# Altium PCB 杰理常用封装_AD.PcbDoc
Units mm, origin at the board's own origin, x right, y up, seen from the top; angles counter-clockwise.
Board outline 121.28 x 58.04 mm, 2 copper layers (Top, Bottom), stack 0.069 mm thick; 26 components, 0 nets, 451 pads, 0 vias.
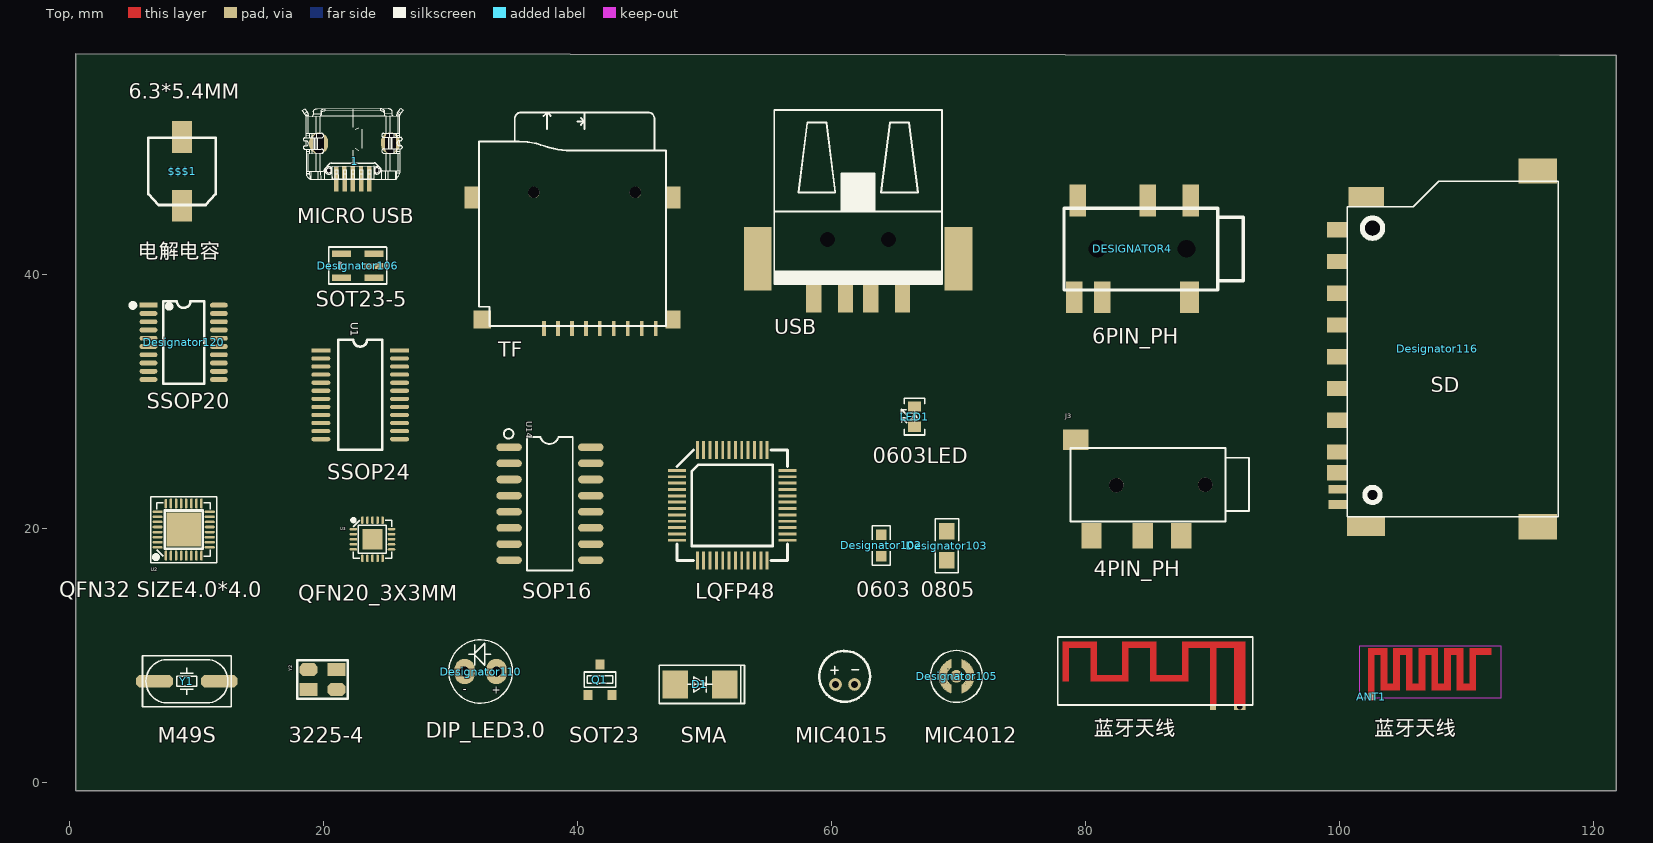
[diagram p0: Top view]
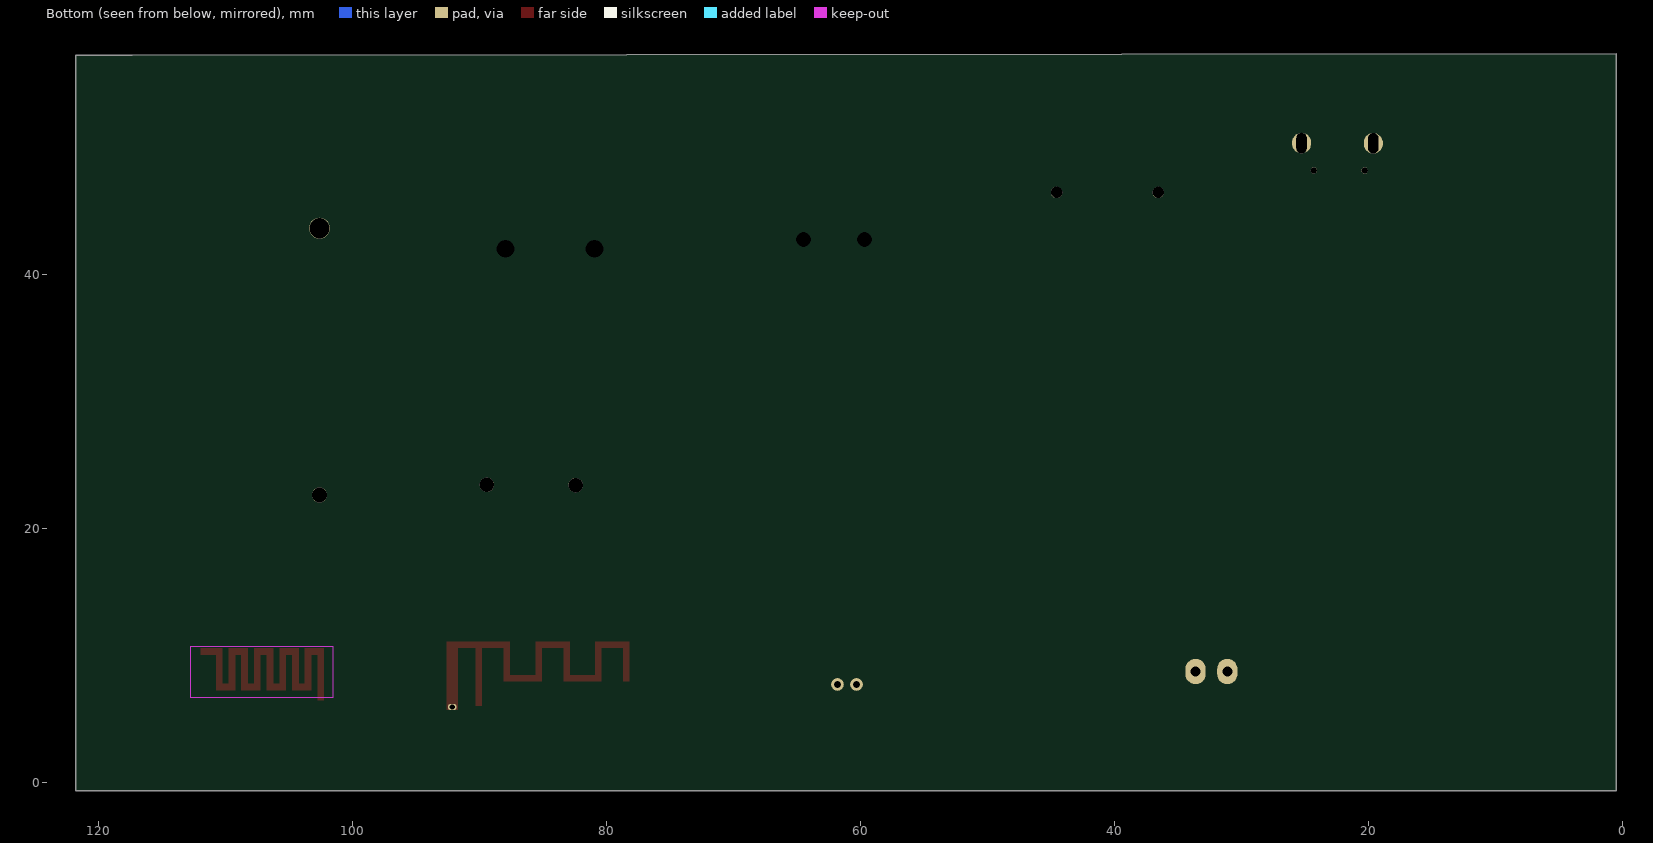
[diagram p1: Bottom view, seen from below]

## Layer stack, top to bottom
Top: signal copper 0.0343
Bottom: signal copper 0.0343

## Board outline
0.508,57.404 0.508,-0.635 10.922,-0.635 121.793,-0.635 121.793,11.43 121.793,57.277 117.348,57.277

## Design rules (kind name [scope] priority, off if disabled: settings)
Clearance "'Default' PADS rule_18" [All] p1: gap=0.3
Clearance "'Default' PADS rule_15" [IsVia vs IsVia] p2: gap=0.305
ComponentClearance "'Default' PADS rule_12" [All] p1: gap=0 collisioncheckmode=3 verticalgap=0.254 showdistances=FALSE
FlightTimeFalling "'Default' PADS rule_10" [All] p1: maximum=10.00g
FlightTimeRising "'Default' PADS rule_9" [All] p1: maximum=10.00g
Length "'Default' PADS rule_5" [All] p1: maxlimit=1270 minlimit=0
MatchedLengths "'Default' PADS rule_11" [InNetClass('All Nets')] p1: tolerance=5.08 checknetsindiffpair=TRUE checkdiffpairvsdiffpair=TRUE checkothers=TRUE
MaxMinImpedance "'Default' PADS rule_8" [All] p1: minimum=50.00 maximum=150.0
ParallelSegment "'Default' PADS rule_7" [All] p1: limit=25.4 gap=5.08
ParallelSegment "'Default' PADS rule_6" [All] p2: limit=25.4 gap=5.08
PlaneClearance "'Default' PADS rule_14" [All] p1: clearance=0.3
PlaneConnect "Power Plane Connect Style - pads with no thermal" [(Name='1-8') Or (Name='1-9') Or (Name='A1-1') Or (Name='A2-1') Or (Name='A3-1') Or (Name='DESIGNATOR4-7') Or (Name='DESIGNATOR4-8') Or (Name='TF1-14') Or (Name='TF1-15') Or (Name='USB1-0') Or (Name='USB1-0/2')] p1: planeconnectstyle=NoConnect reliefexpansion=0.508 reliefentries=4 reliefconductorwidth=0.254 reliefairgap=0.254 // PAD - No Thermal Connect Rule
PlaneConnect "Power Plane Connect Style - Via from round thru-hole global defaults" [IsVia] p2: planeconnectstyle=Direct reliefexpansion=0.508 reliefentries=4 reliefconductorwidth=0.254 reliefairgap=0.254
PlaneConnect "Power Plane Connect Style - Round thru-hole pad from global defaults" [IsPad And OnMultiLayer And (PadShape_MidLayer1 = 'Round') And (PadXSize_MidLayer1 = PadYSize_MidLayer1)] p3: planeconnectstyle=Direct reliefexpansion=0.508 reliefentries=4 reliefconductorwidth=0.254 reliefairgap=0.254
PlaneConnect "Power Plane Connect Style - Square thru-hole pad from global defaults" [IsPad And OnMultiLayer And ((PadShape_MidLayer1 = 'Rectangular') Or (PadShape_MidLayer1 = 'Octagonal') Or (PadShape_MidLayer1 = 'Rounded Rectangle')) And (PadXSize_MidLayer1 = PadYSize_MidLayer1)] p4: planeconnectstyle=Direct reliefexpansion=0.508 reliefentries=4 reliefconductorwidth=0.254 reliefairgap=0.254
PlaneConnect "Power Plane Connect Style - Rect thru-hole pad from global defaults" [IsPad And OnMultiLayer And ((PadShape_MidLayer1 = 'Rectangular') Or (PadShape_MidLayer1 = 'Octagonal') Or (PadShape_MidLayer1 = 'Rounded Rectangle')) And (PadXSize_MidLayer1 <> PadYSize_MidLayer1)] p5: planeconnectstyle=Direct reliefexpansion=0.508 reliefentries=4 reliefconductorwidth=0.254 reliefairgap=0.254
PlaneConnect "Power Plane Connect Style - Square-rect thru-hole pad from global defaults" [IsPad And OnMultiLayer And (PadShape_MidLayer1 = 'Rounded Rectangle') And (PadXSize_MidLayer1 = PadYSize_MidLayer1) And (Pad_CornerRadius_MidLayer1 = '0%')] p6: planeconnectstyle=Direct reliefexpansion=0.508 reliefentries=4 reliefconductorwidth=0.254 reliefairgap=0.254
PlaneConnect "Power Plane Connect Style - Oval thru-hole pad from global defaults" [IsPad And OnMultiLayer And (PadShape_MidLayer1 = 'Round') And (PadXSize_MidLayer1 <> PadYSize_MidLayer1)] p7: planeconnectstyle=Direct reliefexpansion=0.508 reliefentries=4 reliefconductorwidth=0.254 reliefairgap=0.254
PlaneConnect "Power Plane Connect Style - Round-oval thru-hole pad from global defaults" [IsPad And OnMultiLayer And (PadShape_MidLayer1 = 'Rounded Rectangle') And (PadXSize_MidLayer1 = PadYSize_MidLayer1) And (Pad_CornerRadius_MidLayer1 = '100%')] p8: planeconnectstyle=Direct reliefexpansion=0.508 reliefentries=4 reliefconductorwidth=0.254 reliefairgap=0.254
PolygonConnect "Polygon Connect Style - Bottom Round SMD from global defaults" [IsSMTPin And (PadShape_BottomLayer = 'Round') And (PadXSize_BottomLayer = PADYSize_BottomLayer) vs Layer = 'Bottom'] p1: connectstyle=Direct reliefconductorwidth=0.254 reliefentries=4 polygonreliefangle="45 Angle" airgapwidth=0.254
PolygonConnect "Polygon Connect Style - Top Round SMD from global defaults" [IsSMTPin And (PadShape_TopLayer = 'Round') And (PadXSize_TopLayer = PADYSize_TopLayer) vs Layer = 'Top'] p2: connectstyle=Direct reliefconductorwidth=0.254 reliefentries=4 polygonreliefangle="45 Angle" airgapwidth=0.254
PolygonConnect "Polygon Connect Style - Bottom Square SMD from global defaults 1" [IsSMTPin And (PadShape_BottomLayer = 'Rectangular') And (PadXSize_BottomLayer = PADYSize_BottomLayer) vs Layer = 'Bottom'] p3: connectstyle=Direct reliefconductorwidth=0.254 reliefentries=4 polygonreliefangle="45 Angle" airgapwidth=0.254
PolygonConnect "Polygon Connect Style - Bottom Square SMD from global defaults 2" [IsSMTPin And (PadShape_BottomLayer = 'Octagonal') And (PadXSize_BottomLayer = PADYSize_BottomLayer) vs Layer = 'Bottom'] p4: connectstyle=Direct reliefconductorwidth=0.254 reliefentries=4 polygonreliefangle="45 Angle" airgapwidth=0.254
PolygonConnect "Polygon Connect Style - Bottom Square SMD from global defaults 3" [IsSMTPin And (PadShape_BottomLayer = 'Rounded Rectangle') And (PadXSize_BottomLayer = PADYSize_BottomLayer) vs Layer = 'Bottom'] p5: connectstyle=Direct reliefconductorwidth=0.254 reliefentries=4 polygonreliefangle="45 Angle" airgapwidth=0.254
PolygonConnect "Polygon Connect Style - Top Square SMD from global defaults 1" [IsSMTPin And (PadShape_TopLayer = 'Rectangular') And (PadXSize_TopLayer = PADYSize_TopLayer) vs Layer = 'Top'] p6: connectstyle=Direct reliefconductorwidth=0.254 reliefentries=4 polygonreliefangle="45 Angle" airgapwidth=0.254
PolygonConnect "Polygon Connect Style - Top Square SMD from global defaults 2" [IsSMTPin And (PadShape_TopLayer = 'Octagonal') And (PadXSize_TopLayer = PADYSize_TopLayer) vs Layer = 'Top'] p7: connectstyle=Direct reliefconductorwidth=0.254 reliefentries=4 polygonreliefangle="45 Angle" airgapwidth=0.254
PolygonConnect "Polygon Connect Style - Top Square SMD from global defaults 3" [IsSMTPin And (PadShape_TopLayer = 'Rounded Rectangle') And (PadXSize_TopLayer = PADYSize_TopLayer) vs Layer = 'Top'] p8: connectstyle=Direct reliefconductorwidth=0.254 reliefentries=4 polygonreliefangle="45 Angle" airgapwidth=0.254
PolygonConnect "Polygon Connect Style - Bottom Rect SMD from global defaults 1" [IsSMTPin And (PadShape_BottomLayer = 'Rectangular') And (PadXSize_BottomLayer <> PADYSize_BottomLayer) vs Layer = 'Bottom'] p9: connectstyle=Direct reliefconductorwidth=0.254 reliefentries=4 polygonreliefangle="45 Angle" airgapwidth=0.254
PolygonConnect "Polygon Connect Style - Bottom Rect SMD from global defaults 2" [IsSMTPin And (PadShape_BottomLayer = 'Octagonal') And (PadXSize_BottomLayer <> PADYSize_BottomLayer) vs Layer = 'Bottom'] p10: connectstyle=Direct reliefconductorwidth=0.254 reliefentries=4 polygonreliefangle="45 Angle" airgapwidth=0.254
PolygonConnect "Polygon Connect Style - Bottom Rect SMD from global defaults 3" [IsSMTPin And (PadShape_BottomLayer = 'Rounded Rectangle') And (PadXSize_BottomLayer <> PADYSize_BottomLayer) vs Layer = 'Bottom'] p11: connectstyle=Direct reliefconductorwidth=0.254 reliefentries=4 polygonreliefangle="45 Angle" airgapwidth=0.254
PolygonConnect "Polygon Connect Style - Bottom Square-rect SMD pad from global defaults" [IsSMTPin And (PadShape_BottomLayer = 'Rounded Rectangle') And (PadXSize_BottomLayer = PADYSize_BottomLayer) And (Pad_CornerRadius_BottomLayer = '0%') vs Layer = 'Bottom'] p12: connectstyle=Direct reliefconductorwidth=0.254 reliefentries=4 polygonreliefangle="45 Angle" airgapwidth=0.254
PolygonConnect "Polygon Connect Style - Top Rect SMD from global defaults 1" [IsSMTPin And (PadShape_TopLayer = 'Rectangular') And (PadXSize_TopLayer <> PADYSize_TopLayer) vs Layer = 'Top'] p13: connectstyle=Direct reliefconductorwidth=0.254 reliefentries=4 polygonreliefangle="45 Angle" airgapwidth=0.254
PolygonConnect "Polygon Connect Style - Top Rect SMD from global defaults 2" [IsSMTPin And (PadShape_TopLayer = 'Octagonal') And (PadXSize_TopLayer <> PADYSize_TopLayer) vs Layer = 'Top'] p14: connectstyle=Direct reliefconductorwidth=0.254 reliefentries=4 polygonreliefangle="45 Angle" airgapwidth=0.254
PolygonConnect "Polygon Connect Style - Top Rect SMD from global defaults 3" [IsSMTPin And (PadShape_TopLayer = 'Rounded Rectangle') And (PadXSize_TopLayer <> PADYSize_TopLayer) vs Layer = 'Top'] p15: connectstyle=Direct reliefconductorwidth=0.254 reliefentries=4 polygonreliefangle="45 Angle" airgapwidth=0.254
PolygonConnect "Polygon Connect Style - Top Square-rect SMD pad from global defaults" [IsSMTPin And (PadShape_TopLayer = 'Rounded Rectangle') And (PadXSize_TopLayer = PADYSize_TopLayer) And (Pad_CornerRadius_TopLayer = '0%') vs Layer = 'Top'] p16: connectstyle=Direct reliefconductorwidth=0.254 reliefentries=4 polygonreliefangle="45 Angle" airgapwidth=0.254
PolygonConnect "Polygon Connect Style - Bottom Oval SMD from global defaults" [IsSMTPin And (PadShape_BottomLayer = 'Round') And (PadXSize_BottomLayer <> PADYSize_BottomLayer) vs Layer = 'Bottom'] p17: connectstyle=Direct reliefconductorwidth=0.254 reliefentries=4 polygonreliefangle="45 Angle" airgapwidth=0.254
PolygonConnect "Polygon Connect Style - Bottom Round-oval SMD pad from global defaults" [IsSMTPin And (PadShape_BottomLayer = 'Rounded Rectangle') And (PadXSize_BottomLayer = PADYSize_BottomLayer) And (Pad_CornerRadius_BottomLayer = '100%') vs Layer = 'Bottom'] p18: connectstyle=Direct reliefconductorwidth=0.254 reliefentries=4 polygonreliefangle="45 Angle" airgapwidth=0.254
PolygonConnect "Polygon Connect Style - Top Oval SMD from global defaults" [IsSMTPin And (PadShape_TopLayer = 'Round') And (PadXSize_TopLayer <> PADYSize_TopLayer) vs Layer = 'Top'] p19: connectstyle=Direct reliefconductorwidth=0.254 reliefentries=4 polygonreliefangle="45 Angle" airgapwidth=0.254
PolygonConnect "Polygon Connect Style - Top Round-oval SMD pad from global defaults" [IsSMTPin And (PadShape_TopLayer = 'Rounded Rectangle') And (PadXSize_TopLayer = PADYSize_TopLayer) And (Pad_CornerRadius_TopLayer = '100%') vs Layer = 'Top'] p20: connectstyle=Direct reliefconductorwidth=0.254 reliefentries=4 polygonreliefangle="45 Angle" airgapwidth=0.254
PolygonConnect "Polygon Connect Style - Via from round thru-hole global defaults_19" [IsVia] p21: connectstyle=Direct reliefconductorwidth=0.254 reliefentries=4 polygonreliefangle="45 Angle" airgapwidth=0.254
PolygonConnect "Polygon Connect Style - Bottom Round thru-hole pad from global defaults" [IsPad And OnMultiLayer And (PadShape_BottomLayer = 'Round') And (PadXSize_BottomLayer = PADYSize_BottomLayer) vs Layer = 'Bottom'] p22: connectstyle=Direct reliefconductorwidth=0.254 reliefentries=4 polygonreliefangle="45 Angle" airgapwidth=0.254
PolygonConnect "Polygon Connect Style - Via from round thru-hole global defaults" [IsVia] p23: connectstyle=Direct reliefconductorwidth=0.254 reliefentries=4 polygonreliefangle="45 Angle" airgapwidth=0.254
PolygonConnect "Polygon Connect Style - Top Round thru-hole pad from global defaults" [IsPad And OnMultiLayer And (PadShape_TopLayer = 'Round') And (PadXSize_TopLayer = PADYSize_TopLayer) vs Layer = 'Top'] p24: connectstyle=Direct reliefconductorwidth=0.254 reliefentries=4 polygonreliefangle="45 Angle" airgapwidth=0.254
PolygonConnect "Polygon Connect Style - Bottom Square thru-hole pad from global defaults" [IsPad And OnMultiLayer And ((PadShape_BottomLayer = 'Rectangular') Or (PadShape_BottomLayer = 'Octagonal') Or (PadShape_BottomLayer = 'Rounded Rectangle')) And (PadXSize_BottomLayer = PADYSize_BottomLayer) vs Layer = 'Bottom'] p25: connectstyle=Direct reliefconductorwidth=0.254 reliefentries=4 polygonreliefangle="45 Angle" airgapwidth=0.254
PolygonConnect "Polygon Connect Style - Top Square thru-hole pad from global defaults" [IsPad And OnMultiLayer And ((PadShape_TopLayer = 'Rectangular') Or (PadShape_TopLayer = 'Octagonal') Or (PadShape_TopLayer = 'Rounded Rectangle')) And (PadXSize_TopLayer = PADYSize_TopLayer) vs Layer = 'Top'] p26: connectstyle=Direct reliefconductorwidth=0.254 reliefentries=4 polygonreliefangle="45 Angle" airgapwidth=0.254
PolygonConnect "Polygon Connect Style - Bottom Rect thru-hole pad from global defaults" [IsPad And OnMultiLayer And ((PadShape_BottomLayer = 'Rectangular') Or (PadShape_BottomLayer = 'Octagonal') Or (PadShape_BottomLayer = 'Rounded Rectangle')) And (PadXSize_BottomLayer <> PADYSize_BottomLayer) vs Layer = 'Bottom'] p27: connectstyle=Direct reliefconductorwidth=0.254 reliefentries=4 polygonreliefangle="45 Angle" airgapwidth=0.254
PolygonConnect "Polygon Connect Style - Bottom Square-rect thru-hole pad from global defaults" [IsPad And OnMultiLayer And (PadShape_BottomLayer = 'Rounded Rectangle') And (PadXSize_BottomLayer = PADYSize_BottomLayer) And (Pad_CornerRadius_BottomLayer = '0%') vs Layer = 'Bottom'] p28: connectstyle=Direct reliefconductorwidth=0.254 reliefentries=4 polygonreliefangle="45 Angle" airgapwidth=0.254
PolygonConnect "Polygon Connect Style - Top Rect thru-hole pad from global defaults" [IsPad And OnMultiLayer And ((PadShape_TopLayer = 'Rectangular') Or (PadShape_TopLayer = 'Octagonal') Or (PadShape_TopLayer = 'Rounded Rectangle')) And (PadXSize_TopLayer <> PADYSize_TopLayer) vs Layer = 'Top'] p29: connectstyle=Direct reliefconductorwidth=0.254 reliefentries=4 polygonreliefangle="45 Angle" airgapwidth=0.254
PolygonConnect "Polygon Connect Style - Top Square-rect thru-hole pad from global defaults" [IsPad And OnMultiLayer And (PadShape_TopLayer = 'Rounded Rectangle') And (PadXSize_TopLayer = PADYSize_TopLayer) And (Pad_CornerRadius_TopLayer = '0%') vs Layer = 'Top'] p30: connectstyle=Direct reliefconductorwidth=0.254 reliefentries=4 polygonreliefangle="45 Angle" airgapwidth=0.254
PolygonConnect "Polygon Connect Style - Bottom Oval thru-hole pad from global defaults" [IsPad And OnMultiLayer And (PadShape_BottomLayer = 'Round') And (PadXSize_BottomLayer <> PADYSize_BottomLayer) vs Layer = 'Bottom'] p31: connectstyle=Direct reliefconductorwidth=0.254 reliefentries=4 polygonreliefangle="45 Angle" airgapwidth=0.254
PolygonConnect "Polygon Connect Style - Bottom Round-oval thru-hole pad from global defaults" [IsPad And OnMultiLayer And (PadShape_BottomLayer = 'Rounded Rectangle') And (PadXSize_BottomLayer = PADYSize_BottomLayer) And (Pad_CornerRadius_BottomLayer = '100%') vs Layer = 'Bottom'] p32: connectstyle=Direct reliefconductorwidth=0.254 reliefentries=4 polygonreliefangle="45 Angle" airgapwidth=0.254
PolygonConnect "Polygon Connect Style - Top Oval thru-hole pad from global defaults" [IsPad And OnMultiLayer And (PadShape_TopLayer = 'Round') And (PadXSize_TopLayer <> PADYSize_TopLayer) vs Layer = 'Top'] p33: connectstyle=Direct reliefconductorwidth=0.254 reliefentries=4 polygonreliefangle="45 Angle" airgapwidth=0.254
PolygonConnect "Polygon Connect Style - Top Round-oval thru-hole pad from global defaults" [IsPad And OnMultiLayer And (PadShape_TopLayer = 'Rounded Rectangle') And (PadXSize_TopLayer = PADYSize_TopLayer) And (Pad_CornerRadius_TopLayer = '100%') vs Layer = 'Top'] p34: connectstyle=Direct reliefconductorwidth=0.254 reliefentries=4 polygonreliefangle="45 Angle" airgapwidth=0.254
PolygonConnect [All] p35: connectstyle=Relief reliefconductorwidth=0.254 reliefentries=4 polygonreliefangle="90 Angle" airgapwidth=0.254
RoutingLayers "'Default' PADS rule_3" [All] p1: top layer_v5=TRUE bottom layer_v5=TRUE
RoutingPriority "'Default' PADS rule_2" [All] p1: routingpriority=3
RoutingTopology "'Default' PADS rule" [All] p1: topology=Shortest
RoutingVias "'Default' PADS rule_4" [All] p1: holewidth=0.4 width=0.6 viastyle="Through Hole" minholewidth=0.4 minwidth=0.6 maxholewidth=0.4 maxwidth=0.6
SMDToCorner "'Default' PADS rule_16" [All] p1: distance=120000
SMDToPlane "'Default' PADS rule_17" [All] p1: distance=120000
SolderMaskExpansion [All] p1: expansion=0.102
Width "'Default' PADS rule_13" [All] p1: maxlimit=3.048 minlimit=0.152 preferedwidth=0.3
22 further rules are at their usual default settings.

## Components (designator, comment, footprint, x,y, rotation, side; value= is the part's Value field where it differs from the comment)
1 "MICROUSB" MICROUSB 22.03,50.268 r0 top
$$$1 "6.3V/100UF" 6.3V/100UF 8.89,48.133 r270 top
ANT1 "ANT-BLUE1A" ANT-BLUE1A 102.489,5.334 r0 top
D1 "D-SOD-214" D-SOD-214 49.657,7.747 r0 top
DESIGNATOR4 "PJ-320D-3.5" PJ-320D-3.5 83.693,42.037 r270 top
Designator102 "Comment" 0603R 64,18.664 r90 top
Designator103 "Comment" 0805MINI 69.08,18.664 r270 top
Designator105 "Comment" 4013_MIC 69.85,8.382 r180 top
Designator106 "Comment" 4054 22.86,40.259 r180 top
Designator110 "Comment" LED-5.0 32.385,8.763 r180 top
Designator116 "Comment" SD-D 107.696,34.163 r180 top
Designator120 "Comment" TSSOP20 9.017,34.671 r0 top
J3 "JACK-4PIN" JACK-4PIN 84.328,23.241 r0 top
LED1 "LED_0603" LED_0603 66.548,28.829 r90 top
Q1 "SOT-23" SOT-23 41.783,8.128 r180 top
U1 "" QSOP24 19.812,34.036 r0 top
U2 "QFN32_2" QFN32_2 9.017,19.939 r90 top
U3 "QFN20_3X3MM" QFN20_3X3MM 23.876,19.177 r0 top
Y1 "Y-M49/S2.4MM" Y-M49/S2.4MM 9.271,8.001 r180 top
Y2 "3225_4" 3225_4 19.939,8.128 r0 top
? "TFAA" TFAA 39.624,41.123 r180 top
? "USB-SMT" USB-SMT 62.103,40.513 r180 top
? "BT_ANT" IFA 90.043,5.969 r180 top
? "Comment" "SOP16 - duplicate" 37.846,21.971 r0 top
? "MIN-4015" MIN-4015 60.325,7.747 r180 top
? "Comment" LQFP48 52.197,21.844 r0 top

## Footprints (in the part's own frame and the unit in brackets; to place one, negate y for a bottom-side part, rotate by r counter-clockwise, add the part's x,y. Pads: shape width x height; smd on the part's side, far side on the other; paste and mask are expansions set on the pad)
6.3V/100UF [mm]
  rect 2.5x1.6 smd: 1(2.7,0) 2(-2.7,0)
  silkscreen extent -2.65,-2.65 2.65,2.65
0603R [mm]
  rect 0.8x0.8 smd: 1(0.87,0.07) 2(-0.83,0.07)
  silkscreen extent -1.53,-0.63 1.57,0.77
0805MINI [mm]
  rect 1.3x1.2 smd: 1(-1.148,0.008) 2(1.138,0.008)
  silkscreen extent -2.14,-0.9 2.13,0.95
3225_4 [mm]
  rect 1.4x1 smd mask+0.025: 1(-1.097,-0.776) 2(1.103,0.788)
  oct 1.4x1 smd mask+0.025: 3(1.103,-0.776) 4(-1.097,0.788)
  silkscreen extent -2,-1.52 2,1.53
4013_MIC [mm]
  round 0.005 smd: 1(0.401,1.351) 1(0.401,1.351)
  rect 0.5x0.4 smd: M+(-0.65,-0.863) M+(0.65,0.857) M-(-1.02,-0.053) M-(-1.02,0.257) M-(-0.65,0.857) M-(0.65,-0.863) M-(1.02,-0.263) M-(1.02,0.047)
  rect 0.3x0.3 smd: M+(-0.55,-1.073) M+(0.55,1.067) M-(-1.208,-0.074) M-(-1.165,0.193) M-(-0.55,1.067) M-(0.55,-1.073) M-(1.165,-0.199) M-(1.208,0.068)
  round 1 smd: M+(0,-0.003)
  rect 0.1x0.1 smd rot 179: M-(-1.364,0.01) M-(1.364,-0.016)
  rect 0.1x0.1 smd rot 5: M-(-1.361,-0.084) M-(1.361,0.078)
  rect 0.1x0.1 smd rot 176: M-(-1.361,0.106) M-(1.361,-0.112)
  rect 0.1x0.1 smd rot 7: M-(-1.351,-0.181) M-(1.351,0.175)
  rect 0.1x0.1 smd rot 171: M-(-1.35,0.201) M-(1.35,-0.207)
  rect 0.1x0.1 smd rot 11: M-(-1.336,-0.273) M-(1.336,0.267)
  rect 0.1x0.1 smd rot 166: M-(-1.331,0.294) M-(1.331,-0.3)
  rect 0.1x0.1 smd rot 15: M-(-1.313,-0.367) M-(1.313,0.361)
  rect 0.1x0.1 smd rot 163: M-(-1.305,0.387) M-(1.305,-0.393)
  rect 0.1x0.1 smd rot 20: M-(-1.285,-0.457) M-(1.285,0.451)
  rect 0.1x0.1 smd rot 159: M-(-1.274,0.478) M-(1.274,-0.484)
  rect 0.1x0.1 smd rot 24: M-(-1.249,-0.546) M-(1.249,0.54)
  rect 0.1x0.1 smd rot 155: M-(-1.236,0.567) M-(1.236,-0.573)
  rect 0.1x0.1 smd rot 26: M-(-1.207,-0.634) M-(1.207,0.628)
  rect 0.1x0.1 smd rot 152: M-(-1.191,0.653) M-(1.191,-0.659)
  rect 0.1x0.1 smd rot 32: M-(-1.161,-0.716) M-(1.161,0.71)
  rect 0.3x0.3 smd rot 101: M-(-1.157,-0.322) M-(1.157,0.316)
  rect 0.1x0.1 smd rot 147: M-(-1.143,0.735) M-(1.143,-0.741)
  rect 0.3x0.3 smd rot 61: M-(-1.113,0.438) M-(-0.677,0.957) M-(0.677,-0.963) M-(1.113,-0.444)
  rect 0.1x0.1 smd rot 35: M-(-1.108,-0.796) M-(1.108,0.79)
  rect 0.1x0.1 smd rot 144: M-(-1.089,0.814) M-(1.089,-0.82)
  rect 0.3x0.3 smd rot 104: M-(-1.076,-0.522) M-(1.076,0.516)
  rect 0.1x0.1 smd rot 39: M-(-1.052,-0.87) M-(1.052,0.864)
  rect 0.1x0.1 smd rot 139: M-(-1.03,0.888) M-(1.03,-0.894)
  rect 0.1x0.1 smd rot 45: M-(-0.989,-0.94) M-(0.989,0.934)
  rect 0.4x0.5 smd: M-(-0.97,-0.503) M-(-0.97,0.517) M-(0.97,-0.523) M-(0.97,0.497)
  rect 0.1x0.1 smd rot 135: M-(-0.965,0.958) M-(0.965,-0.964)
  rect 0.1x0.1 smd rot 46: M-(-0.92,-1.008) M-(0.92,1.002)
  rect 0.3x0.3 smd rot 45: M-(-0.907,0.765) M-(0.907,-0.771)
  rect 0.3x0.3 smd rot 124: M-(-0.906,-0.798) M-(0.906,0.792)
  rect 0.1x0.1 smd rot 130: M-(-0.9,1.017) M-(0.9,-1.023)
  rect 0.1x0.3 smd rot 105: M-(-0.892,-0.244) M-(0.892,0.238)
  rect 0.1x0.3 smd rot 110: M-(-0.865,-0.327) M-(0.865,0.321)
  rect 0.1x0.1 smd rot 53: M-(-0.849,-1.069) M-(0.849,1.063)
  rect 0.1x0.1 smd rot 126: M-(-0.83,1.077) M-(0.83,-1.083)
  rect 0.1x0.3 smd rot 115: M-(-0.829,-0.412) M-(0.829,0.406)
  rect 0.1x0.3 smd rot 9: M-(-0.81,-0.156) M-(0.81,0.15)
  rect 0.1x0.3 smd rot 121: M-(-0.806,-0.458) M-(0.806,0.452)
  rect 0.1x0.3 smd rot 168: M-(-0.805,0.161) M-(0.805,-0.167)
  rect 0.1x0.3 smd rot 158: M-(-0.773,0.477) M-(0.773,-0.483)
  rect 0.1x0.3 smd rot 56: M-(-0.771,0.501) M-(0.771,-0.507)
  rect 0.1x0.1 smd rot 55: M-(-0.771,-1.126) M-(0.771,1.12)
  rect 0.1x0.3 smd rot 126: M-(-0.767,-0.519) M-(0.767,0.513)
  rect 0.1x0.1 smd rot 123: M-(-0.76,1.127) M-(0.76,-1.133)
  rect 0.1x0.3 smd rot 157: M-(-0.735,0.364) M-(0.735,-0.37)
  rect 0.1x0.3 smd rot 53: M-(-0.712,0.584) M-(0.712,-0.59)
  rect 0.1x0.3 smd rot 129: M-(-0.712,-0.591) M-(0.712,0.585)
  rect 0.3x0.3 smd rot 133: M-(-0.691,-0.982) M-(0.691,0.976)
  rect 0.1x0.1 smd rot 60: M-(-0.691,-1.177) M-(0.691,1.171)
  rect 0.1x0.1 smd rot 120: M-(-0.679,1.175) M-(0.68,-1.183)
  rect 0.1x0.3 smd rot 47: M-(-0.648,0.656) M-(0.648,-0.662)
  rect 0.1x0.3 smd rot 136: M-(-0.643,-0.666) M-(0.643,0.66)
  rect 0.1x0.1 smd rot 115: M-(-0.62,1.207) M-(0.62,-1.213)
  rect 0.3x0.3 smd rot 53: M-(-0.617,-0.694) M-(0.617,0.688)
  rect 0.1x0.1 smd rot 64: M-(-0.607,-1.222) M-(0.607,1.216)
  rect 0.1x0.3 smd rot 43: M-(-0.586,0.713) M-(0.586,-0.719)
  rect 0.1x0.1 smd rot 114: M-(-0.543,1.24)
  rect 0.1x0.3 smd rot 33: M-(-0.526,0.757) M-(0.526,-0.763)
  rect 0.1x0.1 smd rot 67: M-(-0.52,-1.262) M-(0.52,1.256)
  rect 0.1x0.1 smd rot 110: M-(-0.48,1.267) M-(0.48,-1.273)
  rect 0.1x0.1 smd rot 61: M-(-0.476,1.206) M-(0.472,-1.198)
  rect 0.1x0.1 smd rot 70: M-(-0.464,-1.284) M-(0.464,1.278)
  rect 0.1x0.1 smd: M-(-0.45,-1.271) M-(0.45,1.265)
  rect 0.02x0.02 smd rot 108: M-(-0.438,1.325) M-(-0.42,1.331) M-(0.42,-1.337) M-(0.438,-1.331)
  rect 0.05x0.05 smd: M-(-0.425,1.239) M-(-0.425,1.279) M-(-0.425,1.306) M-(0.425,-1.312) M-(0.425,-1.285) M-(0.425,-1.245)
  rect 0.02x0.02 smd rot 162: M-(-0.423,-1.341) M-(0.423,1.335)
  rect 0.02x0.02 smd: M-(-0.422,-1.329) M-(-0.41,1.331) M-(-0.41,-1.342) M-(-0.41,-1.329) M-(0.41,1.323) M-(0.41,1.336) M-(0.41,-1.337) M-(0.422,1.323)
  rect 0.01x0.01 smd rot 71: M-(-0.411,-1.35) M-(0.411,1.344)
  rect 0.01x0.01 smd rot 16: M-(-0.408,1.34) M-(0.408,-1.346)
  rect 0.01x0.01 smd rot 179: M-(-0.405,1.339) M-(0.405,-1.345)
  rect 0.01x0.01 smd rot 89: M-(-0.405,-1.351) M-(0.405,1.345)
  rect 0.005x0.005 smd rot 17: M-(-0.403,1.344) M-(0.403,-1.35)
  rect 0.1x0.1 smd rot 112: M-(0.54,-1.253)
  silkscreen extent -2.05,-2.05 2.05,2.05
4054 [mm]
  round 0.5 on Top Overlay: 0(-0.09,0.52)
  rect 1.5x0.508 smd: 1(-1.13,0.515) 2(-1.13,-0.425) 3(-1.13,-1.39) 4(1.41,-1.39) 5(1.41,0.515)
  silkscreen extent -2.14,-1.91 2.42,0.99
ANT-BLUE1A [mm]
  rect 0.5x0.5 smd: 1(0.015,1.445)
  Top region: -0.25,1.155 0.25,1.155 0.25,4.75 0.75,4.75 0.75,1.95 2.25,1.95 2.25,4.75 2.75,4.75 2.75,1.95 4.25,1.95 4.25,4.75 4.75,4.75 4.75,1.95 6.25,1.95 6.25,4.75 6.75,4.75 6.75,1.95 8.25,1.95 8.25,4.75 9.45,4.75 9.45,5.25 7.75,5.25 7.75,2.45 7.25,2.45 7.25,5.25 5.75,5.25 5.75,2.45 5.25,2.45 5.25,5.25 3.75,5.25 3.75,2.45 3.25,2.45 3.25,5.25 1.75,5.25 1.75,2.45 1.25,2.45 1.25,5.25 -0.25,5.25 -0.25,1.155
  Keep-Out Layer pour cut-out: 10.25,5.432 -0.931,5.432 -0.931,1.364 10.25,1.364 10.25,5.432
D-SOD-214 [mm]
  rect 2x2.2 smd: 1(-1.95,0) 2(1.95,0)
  silkscreen extent -3.2,-1.5 3.5,1.5
IFA [mm]
  rect 0.5x0.5 smd mask+0.003: 1(0,0)
  rect 0.9x0.5 smd mask+0.003: 2(-2.1,0)
  oval 0.7x0.5 hole 0.4 mask+0.01: 2(-2.1,0)
  rect 0.9x0.5 on Top Solder mask+0.003: 2(-2.1,0)
  rect 0.5x0.5 on Top Solder mask+0: ""(-2.3,-4.9)
  rect 0.5x0.5 on Top Solder mask+0.003: ""(0,0) ""(0,-4.4) ""(2.2,-2.26) ""(2.2,-4.9) ""(4.7,-2.26) ""(4.7,-4.9) ""(6.9,-4.9) ""(6.9,-2.26) ""(9.4,-4.9) ""(9.4,-2.26) ""(11.6,-4.9) ""(11.6,-2.26)
  Top region: 11.35,-2.01 11.35,-5.15 11.85,-5.15 11.85,-2.01
  Top region: 9.15,-4.651 9.15,-5.15 11.85,-5.15 11.85,-4.651
  Top region: 9.65,-2.51 9.65,-2.01 6.949,-2.01 6.949,-2.51
  Top region: 9.15,-2.01 9.15,-5.15 9.65,-5.15 9.65,-2.01
  Top region: 1.95,-2.01 1.95,-5.15 2.45,-5.15 2.45,-2.01
  Top region: -0.251,-0.092 -0.251,-4.9 0.25,-4.9 0.25,-0.092
  Top region: -2.549,0.25 -2.549,-5.15 -1.65,-5.15 -1.65,0.25
  Top region: 1.95,-2.01 1.95,-2.51 4.95,-2.51 4.95,-2.01
  Top region: 4.449,-2.01 4.449,-5.15 4.95,-5.15 4.95,-2.01
  Top region: 4.449,-4.65 4.449,-5.15 7.15,-5.15 7.15,-4.65
  Top region: 6.65,-2.01 6.65,-5.15 7.15,-5.15 7.15,-2.01
  Top lines w0.5: 2.2,-4.9 -2.3,-4.9
  silkscreen extent -3.12,-5.53 12.23,-0.18
JACK-4PIN [mm]
  rect 1.6x2 smd: 1(3.201,-3.776) 2(0.177,-3.776) 3(-3.849,-3.776)
  rect 2x1.6 smd: 4(-5.097,3.773)
  round 1.143 hole 1.143: 5(-1.892,0.194) 6(5.093,0.219)
  silkscreen extent -5.5,-2.68 8.55,3.12
LED-5.0 [mm]
  oval 1.6x2 hole 0.8: A(-1.25,0) k(1.25,0)
  silkscreen extent -2.5,-2.5 2.5,2.5
LED_0603 [mm]
  rect 0.8x1 smd: 1(-0.8,0) 2(0.8,0)
  silkscreen extent -1.45,-0.8 1.45,1.03
LQFP48 [mm]
  rect 1.4x0.229 smd: 1(-4.35,2.75) 2(-4.35,2.25) 3(-4.35,1.75) 4(-4.35,1.25) 5(-4.35,0.75) 6(-4.35,0.25) 7(-4.35,-0.25) 8(-4.35,-0.75) 9(-4.35,-1.25) 10(-4.35,-1.75) 11(-4.35,-2.25) 12(-4.35,-2.75) 25(4.35,-2.75) 26(4.35,-2.25) 27(4.35,-1.75) 28(4.35,-1.25) 29(4.35,-0.75) 30(4.35,-0.25) 31(4.35,0.25) 32(4.35,0.75) 33(4.35,1.25) 34(4.35,1.75) 35(4.35,2.25) 36(4.35,2.75)
  rect 0.229x1.4 smd: 13(-2.75,-4.35) 14(-2.25,-4.35) 15(-1.75,-4.35) 16(-1.25,-4.35) 17(-0.75,-4.35) 18(-0.25,-4.35) 19(0.25,-4.35) 20(0.75,-4.35) 21(1.25,-4.35) 22(1.75,-4.35) 23(2.25,-4.35) 24(2.75,-4.35) 37(2.75,4.35) 38(2.25,4.35) 39(1.75,4.35) 40(1.25,4.35) 41(0.75,4.35) 42(0.25,4.35) 43(-0.25,4.35) 44(-0.75,4.35) 45(-1.25,4.35) 46(-1.75,4.35) 47(-2.25,4.35) 48(-2.75,4.35)
  silkscreen extent -4.35,-4.35 4.35,4.35
MICROUSB [mm]
  rect 2x0.35 smd rot 90.18: 1(1.597,-2.725) 2(0.947,-2.727) 3(0.297,-2.729) 4(-0.353,-2.731) 5(-1.003,-2.733)
  oval 1.7x1.5 / inner oval 1.7x1.5 / far side oval 1.62x1.5 hole 0.8 slot 1.6 at 90 deg rot 90.18: 6(-2.387,0.073) 7(3.263,0.09)
  round 0.5 / inner round 0.7 / far side round 0.5 hole 0.5 unplated: 8(-1.705,-2.067) 9(2.295,-2.063)
  silkscreen extent -3.69,-2.77 4.27,2.82
MIN-4015 [mm]
  round 1 hole 0.55: 1(0,0) 2(-1.5,0)
  silkscreen extent -2.72,-2.63 1.27,1.36
PJ-320D-3.5 [mm]
  rect 2.5x1.3 smd: 1(-3.81,4.59) 3(-3.81,1.19) 4(-3.81,-4.31) 5(3.81,-2.39) 6(3.81,-4.59)
  rect 2.5x1.5 smd: 2(3.81,4.49)
  round 0.025 hole 1.4: 7(0,4.261) 8(0,-2.739)
  silkscreen extent -3.19,-5.38 3.24,8.72
QFN20_3X3MM [mm]
  oval 0.6x0.2 smd: 1(-1.5,0.8) 2(-1.5,0.4) 3(-1.5,0) 4(-1.5,-0.4) 5(-1.5,-0.8) 11(1.5,-0.8) 12(1.5,-0.4) 13(1.5,0) 14(1.5,0.4) 15(1.5,0.8)
  oval 0.2x0.6 smd: 6(-0.8,-1.5) 7(-0.4,-1.5) 8(0,-1.5) 9(0.4,-1.5) 10(0.8,-1.5) 16(0.8,1.5) 17(0.4,1.5) 18(0,1.5) 19(-0.4,1.5) 20(-0.8,1.5)
  rect 1.6x1.6 smd: 21(0,0)
  silkscreen extent -1.63,-1.5 1.5,1.63
QFN32_2 [mm]
  oval 0.8x0.2 smd: 1(-2.05,1.4) 2(-2.05,1) 3(-2.05,0.6) 4(-2.05,0.2) 5(-2.05,-0.2) 6(-2.05,-0.6) 7(-2.05,-1) 8(-2.05,-1.4) 17(2.05,-1.4) 18(2.05,-1) 19(2.05,-0.6) 20(2.05,-0.2) 21(2.05,0.2) 22/2(2.05,0.6) 23(2.05,1)
  oval 0.2x0.8 smd: 9(-1.4,-2.05) 10(-1,-2.05) 11(-0.6,-2.05) 12(-0.2,-2.05) 13(0.2,-2.05) 14(0.6,-2.05) 15(1,-2.05) 16(1.4,-2.05) 25(1.4,2.05) 26(1,2.05) 27(0.6,2.05) 28(0.2,2.05) 29(-0.2,2.05) 30(-0.6,2.05) 31(-1,2.05) 32(-1.4,2.05)
  rect 2.7x2.7 smd: 22(0,0)
  oval 0.75x0.2 smd: 24(2.04,1.4)
  silkscreen extent -2.6,-2.6 2.6,2.6
QSOP24 [mm]
  rect 1.5x0.33 smd: 1(0,0) 24(6.2,0)
  oval 1.5x0.33 smd: 2(0,-0.635) 3(0,-1.27) 4(0,-1.905) 5(0,-2.54) 6(0,-3.175) 7(0,-3.81) 8(0,-4.445) 9(0,-5.08) 10(0,-5.715) 11(0,-6.35) 12(0,-6.985) 13(6.2,-6.985) 14(6.2,-6.35) 15(6.2,-5.715) 16(6.2,-5.08) 17(6.2,-4.445) 18(6.2,-3.81) 19(6.2,-3.175) 20(6.2,-2.54) 21(6.2,-1.905) 22(6.2,-1.27) 23(6.2,-0.635)
  silkscreen extent 1.36,-7.82 4.84,0.84
SD-D [mm]
  rect 1.6x1.2 smd: 1(7.9,-6.88) 2(7.9,-4.38) 3(7.9,-1.88) 4(7.9,0.63) 5(7.9,3.13) 6(7.9,5.63) 7(7.9,8.13) 8(7.9,9.75) 9(7.9,-9.38)
  rect 1.5x0.7 smd: 10(7.8,11.05) 11(7.8,12.25)
  rect 2.8x1.5 smd: 12(5.6,-12)
  rect 3x1.5 smd: 13(5.6,14)
  rect 3x2 smd: 14(-7.9,-14) 15(-7.9,14)
  round 1.2 / inner round 0 / far side round 1.2 hole 1.2: 16(5.097,11.5)
  round 1.65 / inner round 0 / far side round 1.65 hole 1.6: 17(5.1,-9.498)
  silkscreen extent -9.5,-13.2 7.1,13.2
"SOP16 - duplicate" [mm]
  oval 2x0.6 smd: 1(-3.215,4.445) 2(-3.215,3.175) 3(-3.215,1.905) 4(-3.215,0.635) 5(-3.215,-0.635) 6(-3.215,-1.905) 7(-3.215,-3.175) 8(-3.215,-4.445) 9(3.215,-4.445) 10(3.215,-3.175) 11(3.215,-1.905) 12(3.215,-0.635) 13(3.215,0.635) 14(3.215,1.905) 15(3.215,3.175) 16(3.215,4.445)
  silkscreen extent -3.63,-5.25 1.8,5.88
SOT-23 [mm]
  rect 0.7x0.8 smd: 1(-0.95,1.2) 2(0.95,1.2) 3(0,-1.2)
  silkscreen extent -1.25,-0.6 1.25,0.6
TFAA [mm]
  rect 0.3x1.2 smd: 1(2.25,5.35) 2(1.15,5.35) 3(0.05,5.35) 4(-1.05,5.35) 5(-2.15,5.35) 6(-3.25,5.35) 7(-4.35,5.35) 8(-5.45,5.35) 9(-6.55,5.35)
  rect 1.2x1.4 smd: 10(-7.9,4.65)
  rect 1.4x1.4 smd: 11(7.1,4.65)
  rect 1.2x1.7 smd: 12(-7.9,-4.95) 13(7.9,-4.95)
  round 0.9 hole 0.9 unplated: 14(3.05,-5.35) 15(-4.95,-5.35)
  silkscreen extent -7.35,-11.65 7.35,5.15
TSSOP20 [mm]
  rect 1.4x0.39 smd: 1(-2.77,2.925)
  oval 1.4x0.39 smd: 2(-2.77,2.275) 3(-2.77,1.625) 4(-2.77,0.975) 5(-2.77,0.325) 6(-2.77,-0.325) 7(-2.77,-0.975) 8(-2.77,-1.625) 9(-2.77,-2.275) 10(-2.77,-2.925) 11(2.77,-2.925) 12(2.77,-2.275) 13(2.77,-1.625) 14(2.77,-0.975) 15(2.77,-0.325) 16(2.77,0.325) 17(2.77,0.975) 18(2.77,1.625) 19(2.77,2.275) 20(2.77,2.925)
  silkscreen extent -4.15,-3.25 1.62,3.25
USB-SMT [mm]
  round 1 hole 1.2 unplated: 0(-2.4,-2.25) 0/2(2.4,-2.25)
  rect 2.2x5 smd: 5(7.9,-0.75) 6(-7.9,-0.75)
  rect 1.2x2.5 smd: D+(1,2.25) D-(-1,2.25) GND(3.5,2.25) VCC(-3.5,2.25)
  silkscreen extent -6.6,-12.45 6.6,1.25
Y-M49/S2.4MM [mm]
  oct 2.9x1 smd: 1(-2.55,0) 2(2.55,0)
  silkscreen extent -3.5,-2 3.5,2

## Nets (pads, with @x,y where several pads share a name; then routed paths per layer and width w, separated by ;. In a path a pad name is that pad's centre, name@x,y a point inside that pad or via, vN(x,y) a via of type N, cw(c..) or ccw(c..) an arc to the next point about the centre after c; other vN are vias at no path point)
pads on no net: 1.1 1.2 1.3 1.4 1.5 1.6 1.7 1.8 1.9 $$$1.1 $$$1.2 ?. ?.0 ?.0/2 ?.1 ?.2 ?.3 ?.4 ?.5 ?.6 ?.7 ?.8 ?.9 ?.10 ?.11 ?.12 ?.13 ?.14 ?.15 ?.16 ?.17 ?.18 ?.19 ?.20 ?.21 ?.22 ?.23 ?.24 ?.25 ?.26 ?.27 ?.28 ?.29 ?.30 ?.31 ?.32 ?.33 ?.34 ?.35 ?.36 ?.37 ?.38 ?.39 ?.40 ?.41 ?.42 ?.43 ?.44 ?.45 ?.46 ?.47 ?.48 ?.D+ ?.D- ?.GND ?.VCC ANT1.1 D1.1 D1.2 DESIGNATOR4.1 DESIGNATOR4.2 DESIGNATOR4.3 DESIGNATOR4.4 DESIGNATOR4.5 DESIGNATOR4.6 DESIGNATOR4.7 DESIGNATOR4.8 Designator102.1 Designator102.2 Designator103.1 Designator103.2 Designator105.1 Designator105.M+ Designator105.M- Designator106.0 Designator106.1 Designator106.2 Designator106.3 Designator106.4 Designator106.5 Designator110.A Designator110.k Designator116.1 Designator116.2 Designator116.3 Designator116.4 Designator116.5 Designator116.6 Designator116.7 Designator116.8 Designator116.9 Designator116.10 Designator116.11 Designator116.12 Designator116.13 Designator116.14 Designator116.15 Designator116.16 Designator116.17 Designator120.1 Designator120.2 Designator120.3 Designator120.4 Designator120.5 Designator120.6 Designator120.7 Designator120.8 Designator120.9 Designator120.10 Designator120.11 Designator120.12 Designator120.13 Designator120.14 Designator120.15 Designator120.16 Designator120.17 Designator120.18 Designator120.19 Designator120.20 J3.1 J3.2 J3.3 J3.4 J3.5 J3.6 LED1.1 LED1.2 Q1.1 Q1.2 Q1.3 U1.1 U1.2 U1.3 U1.4 U1.5 U1.6 U1.7 U1.8 U1.9 U1.10 U1.11 U1.12 U1.13 U1.14 U1.15 U1.16 U1.17 U1.18 U1.19 U1.20 U1.21 U1.22 U1.23 U1.24 U2.1 U2.2 U2.3 U2.4 U2.5 U2.6 U2.7 U2.8 U2.9 U2.10 U2.11 U2.12 U2.13 U2.14 U2.15 U2.16 U2.17 U2.18 U2.19 U2.20 U2.21 U2.22 U2.22/2 U2.23 U2.24 U2.25 U2.26 U2.27 U2.28 U2.29 U2.30 U2.31 U2.32 U3.1 U3.2 U3.3 U3.4 U3.5 U3.6 U3.7 U3.8 U3.9 U3.10 U3.11 U3.12 U3.13 U3.14 U3.15 U3.16 U3.17 U3.18 U3.19 U3.20 U3.21 Y1.1 Y1.2 Y2.1 Y2.2 Y2.3 Y2.4

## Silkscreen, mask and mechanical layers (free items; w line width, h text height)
Silkscreen Top:
  text "6.3*5.4MM" at 4.699,53.467 h2
  text "MICRO USB" at 17.966,43.664 h2
  text "电解电容" at 5.461,40.894 h2
  text "SOT23-5" at 19.431,37.465 h1.2
  text "USB" at 55.499,34.925 h2
  text "6PIN_PH" at 80.518,34.544 h1.2
  text "TF" at 33.782,33.147 h2
  text "SD" at 107.188,30.353 h2
  text "SSOP20" at 6.096,29.464 h1.2
  text "0603LED" at 63.246,25.146 h1.2
  text "SSOP24" at 20.32,23.876 h1.2
  text "4PIN_PH" at 80.645,16.256 h1.2
  text "QFN32 SIZE4.0*4.0" at -0.762,14.605 h1.2
  text "0603" at 61.968,14.6 h1.2
  text "0805" at 67.048,14.6 h1.2
  text "SOP16" at 35.687,14.478 h1.2
  text "LQFP48" at 49.276,14.478 h1.2
  text "QFN20_3X3MM" at 18.034,14.351 h1.2
  text "DIP_LED3.0" at 28.067,3.556 h1.2
  text "蓝牙天线" at 80.645,3.35 h2
  text "蓝牙天线" at 102.743,3.35 h2
  text "M49S" at 6.985,3.156 h1.2
  text "3225-4" at 17.272,3.156 h1.2
  text "SOT23" at 39.37,3.156 h1.2
  text "SMA" at 48.133,3.156 h1.2
  text "MIC4015" at 57.15,3.156 h1.2
  text "MIC4012" at 67.31,3.156 h1.2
